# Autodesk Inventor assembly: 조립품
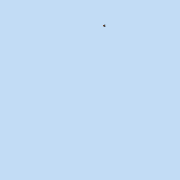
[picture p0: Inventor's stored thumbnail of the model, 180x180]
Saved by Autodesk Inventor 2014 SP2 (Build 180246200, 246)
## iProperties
Created: 2019-01
Part Number: 조립품
Document SubType Name: Assembly
Designer: 거성
Author: 거성
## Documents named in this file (15)
- C:\Users\거성\Desktop\490108v1013\조립품.iam
- C:\Users\거성\Desktop\490108v1013\본체.ipt
- C:\Users\거성\Desktop\490108v1013\베어링 6203.ipt
- C:\Users\거성\Desktop\490108v1013\베어링 6205.ipt
- C:\Users\거성\Desktop\490108v1013\뒤커버.ipt
- C:\Users\거성\Desktop\490108v1013\앞커버.ipt
- C:\Users\거성\Desktop\490108v1013\볼트 M4.ipt
- C:\Users\거성\Desktop\490108v1013\축.ipt
- C:\Users\거성\Desktop\490108v1013\오일 실 17 30 8.ipt
- C:\Users\거성\Desktop\490108v1013\오일 실 25 38 8.ipt
- C:\Users\거성\Desktop\490108v1013\키 5 x 5 x 20.ipt
- C:\Users\거성\Desktop\490108v1013\멈춤나사 M3.ipt
- C:\Users\거성\Desktop\490108v1013\V-벨트풀리.ipt
- C:\Users\거성\Desktop\490108v1013\키 6 x 6 x 18.ipt
- C:\Users\거성\Desktop\490108v1013\스퍼기어.ipt
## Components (1 placed, 1 different names)
1. V-벨트풀리:1 — 각도:2, 각도:3
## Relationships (2: Angle 2)
- 각도:2 [Angle]: V-벨트풀리:1
- 각도:3 [Angle]: V-벨트풀리:1
